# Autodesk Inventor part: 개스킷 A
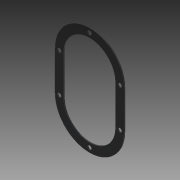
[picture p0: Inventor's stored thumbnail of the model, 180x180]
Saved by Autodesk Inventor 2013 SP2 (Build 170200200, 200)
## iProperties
Created: 2020-04
Part Number: 개스킷 A
Material: 고무
Document SubType Name: Modeling
Designer: mduedu
Density: 0.93 g/cm^3
Mass: 2.61813 g
Surface Area: 62.9733 cm^2
Volume: 2.81519 cm^3
Author: mduedu
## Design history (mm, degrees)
sketch "스케치1"
  geometry: L1 (-40, 0)-(-40, -45); L2 (40, 0)-(40, -45); A1 r 40 centre (0, 0) between (40, 0) and (-40, 0); A2 r 40 centre (0, -45) between (-40, -45) and (40, -45); 1 further point
  constraints: 4 end point, 4 point on circle, 4 tangent, 2 centre point, 1 coincident, 1 equal radius, 1 vertical alignment
  dimensions: "d0" = 80 diameter of A1; "d21" = 45 distance of point (0, 0) A2.centre
extrude "돌출1" new body sketch "스케치1" distance "d1" = 1; taper "d2" = 0 deg
sketch "스케치4"
  geometry: L1 (-30, 0)-(-30, -45); L2 (30, 0)-(30, -45); A1 r 30 centre (0, 0) between (30, 0) and (-30, 0); A2 r 30 centre (0, -45) between (-30, -45) and (30, -45); 1 further point
  constraints: 4 end point, 4 point on circle, 4 tangent, 2 centre point, 1 coincident, 1 equal radius, 1 vertical alignment
  dimensions: "d17" = 60 diameter of A1; "d24" = 45 distance of point (0, 0) A2.centre
extrude "돌출3" cut sketch "스케치4" stored distance "d18" = 1; taper "d19" = 0 deg
sketch "스케치3"
  geometry: A1 r 35 centre (0, 0) between (0, 35) and (-35, 0); A2 r 35 centre (0, -45) between (-35, -45) and (0, -80); 3 further points
  constraints: 6 point on circle, 5 vertical alignment, 3 horizontal alignment, 2 centre point, 1 coincident, 1 equal radius
  dimensions: "d6" = 70 diameter of A1; "d28" = 45 distance of point (0, 0) A2.centre
hole "구멍1" sketch "스케치3" at (0, 35), (-35, 0), (35, 0), (35, -45), (-35, -45), (0, -80) diameter "d7" = 4.5; stored, may be unused: countersink angle "d11" = 90 deg, drill point angle "d13" = 118 deg; dims "d8" = 6, "d9" = 4, "d10" = 2, "d12" = 8
node "솔리드1"
